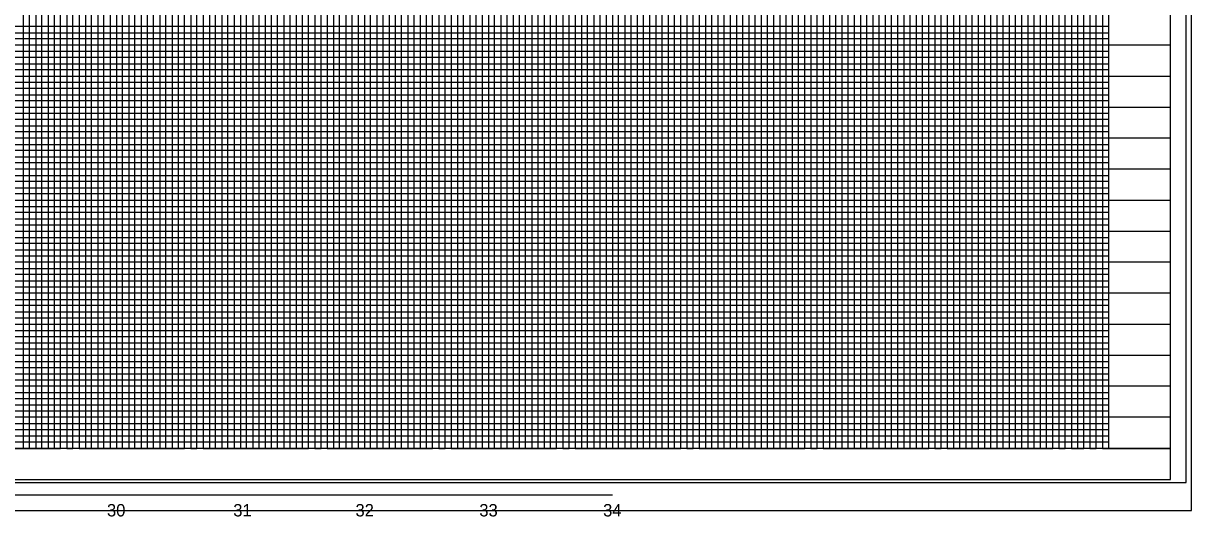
# Model space of a CAD drawing. Extents: x 2345490 to 2436403, y 465165 to 573888.
# Drawn here: x 2383692 to 2384634, y 548958 to 549355 of the extents above; entities that cross this region are included whole.
import ezdxf

# ---------------------------------------------------------------- set-up
doc = ezdxf.new("R2010")
doc.units = 0
for name, color, linetype in [('Old_Level_18', 7, 'Continuous'), ('Old_Level_41', 7, 'Continuous'), ('Old_Level_42', 7, 'Continuous'), ('Old_Level_43', 7, 'Continuous'), ('Old_Level_50', 7, 'Continuous'), ('Old_Level_51', 7, 'Continuous'), ('Old_Level_62', 7, 'Continuous'), ('Old_Level_63', 7, 'Continuous')]:
    doc.layers.add(name, color=color, linetype=linetype)

msp = doc.modelspace()

# ---------------------------------------------------------------- linework, layer by layer
at = {"layer": 'Old_Level_18'}
msp.add_lwpolyline([(2384616.79875, 550037.754), (2383116.79875, 550037.754), (2383116.79875, 548987.754), (2384616.79875, 548987.754)], close=True, dxfattribs=at)
at = {"layer": 'Old_Level_41'}
msp.add_line((2384616.79875, 549012.754), (2383116.79875, 549012.754), dxfattribs=at)
for points in [[(2383641.79875, 549012.754), (2383691.79875, 549012.754), (2383691.79875, 550037.754)], [(2383666.79875, 549012.754), (2383716.79875, 549012.754), (2383716.79875, 550037.754)], [(2383741.79875, 550037.754), (2383741.79875, 549012.754), (2383791.79875, 549012.754), (2383791.79875, 550037.754)], [(2383766.79875, 550037.754), (2383766.79875, 549012.754), (2383816.79875, 549012.754), (2383816.79875, 550037.754)], [(2383841.79875, 550037.754), (2383841.79875, 549012.754), (2383891.79875, 549012.754), (2383891.79875, 550037.754)], [(2383866.79875, 550037.754), (2383866.79875, 549012.754), (2383916.79875, 549012.754), (2383916.79875, 550037.754)], [(2383941.79875, 550037.754), (2383941.79875, 549012.754), (2383991.79875, 549012.754), (2383991.79875, 550037.754)], [(2383966.79875, 550037.754), (2383966.79875, 549012.754), (2384016.79875, 549012.754), (2384016.79875, 550037.754)], [(2384041.79875, 550037.754), (2384041.79875, 549012.754), (2384091.79875, 549012.754), (2384091.79875, 550037.754)], [(2384066.79875, 550037.754), (2384066.79875, 549012.754), (2384116.79875, 549012.754), (2384116.79875, 550037.754)], [(2384141.79875, 550037.754), (2384141.79875, 549012.754), (2384191.79875, 549012.754), (2384191.79875, 550037.754)], [(2384166.79875, 550037.754), (2384166.79875, 549012.754), (2384216.79875, 549012.754), (2384216.79875, 550037.754)], [(2384241.79875, 550037.754), (2384241.79875, 549012.754), (2384291.79875, 549012.754), (2384291.79875, 550037.754)], [(2384266.79875, 550037.754), (2384266.79875, 549012.754), (2384316.79875, 549012.754), (2384316.79875, 550037.754)], [(2384341.79875, 550037.754), (2384341.79875, 549012.754), (2384391.79875, 549012.754), (2384391.79875, 550037.754)], [(2384366.79875, 550037.754), (2384366.79875, 549012.754), (2384416.79875, 549012.754), (2384416.79875, 550037.754)], [(2384441.79875, 549900.204), (2384441.79875, 549012.754), (2384491.79875, 549012.754), (2384491.79875, 549900.204)], [(2384541.79875, 549900.204), (2384541.79875, 549012.754)], [(2384616.79875, 549337.754), (2383116.79875, 549337.754), (2383116.79875, 549287.754), (2384616.79875, 549287.754)], [(2384616.79875, 549262.754), (2383116.79875, 549262.754), (2383116.79875, 549312.754), (2384616.79875, 549312.754)], [(2384616.79875, 549237.754), (2383116.79875, 549237.754), (2383116.79875, 549187.754), (2384616.79875, 549187.754)], [(2384616.79875, 549137.754), (2383116.79875, 549137.754), (2383116.79875, 549087.754), (2384616.79875, 549087.754)], [(2384616.79875, 549062.754), (2383116.79875, 549062.754), (2383116.79875, 549112.754), (2384616.79875, 549112.754)], [(2384616.79875, 549037.754), (2383116.79875, 549037.754)]]:
    msp.add_lwpolyline(points, dxfattribs=at)
at = {"layer": 'Old_Level_42'}
for points in [[(2384466.79875, 549900.204), (2384466.79875, 549012.754), (2384516.79875, 549012.754), (2384516.79875, 549900.204)], [(2384566.79875, 549900.204), (2384566.79875, 549012.754), (2384616.79875, 549012.754)], [(2384616.79875, 549162.754), (2383116.79875, 549162.754), (2383116.79875, 549212.754), (2384616.79875, 549212.754)]]:
    msp.add_lwpolyline(points, dxfattribs=at)
at = {"layer": 'Old_Level_43'}
for points in [[(2383696.79875, 549012.754), (2383696.79875, 550037.754)], [(2383701.79875, 550037.754), (2383701.79875, 549012.754), (2383706.79875, 549012.754), (2383706.79875, 550037.754)], [(2383711.79875, 550037.754), (2383711.79875, 549012.754), (2383721.79875, 549012.754), (2383721.79875, 550037.754)], [(2383726.79875, 550037.754), (2383726.79875, 549012.754), (2383726.79875, 549012.754), (2383731.79875, 549012.754), (2383731.79875, 550037.754)], [(2383736.79875, 550037.754), (2383736.79875, 549012.754), (2383746.79875, 549012.754), (2383746.79875, 550037.754)], [(2383751.79875, 550037.754), (2383751.79875, 549012.754), (2383756.79875, 549012.754), (2383756.79875, 550037.754)], [(2383761.79875, 550037.754), (2383761.79875, 549012.754), (2383771.79875, 549012.754), (2383771.79875, 550037.754)], [(2383776.79875, 550037.754), (2383776.79875, 549012.754), (2383781.79875, 549012.754), (2383781.79875, 550037.754)], [(2383786.79875, 550037.754), (2383786.79875, 549012.754), (2383796.79875, 549012.754), (2383796.79875, 550037.754)], [(2383801.79875, 550037.754), (2383801.79875, 549012.754), (2383806.79875, 549012.754), (2383806.79875, 550037.754)], [(2383811.79875, 550037.754), (2383811.79875, 549012.754), (2383821.79875, 549012.754), (2383821.79875, 550037.754)], [(2383826.79875, 550037.754), (2383826.79875, 549012.754), (2383831.79875, 549012.754), (2383831.79875, 550037.754)], [(2383836.79875, 550037.754), (2383836.79875, 549012.754), (2383846.79875, 549012.754), (2383846.79875, 550037.754)], [(2383851.79875, 550037.754), (2383851.79875, 549012.754), (2383856.79875, 549012.754), (2383856.79875, 550037.754)], [(2383861.79875, 550037.754), (2383861.79875, 549012.754), (2383871.79875, 549012.754), (2383871.79875, 550037.754)], [(2383876.79875, 550037.754), (2383876.79875, 549012.754)], [(2383876.79875, 549012.754), (2383881.79875, 549012.754), (2383881.79875, 550037.154)], [(2383886.79875, 550037.154), (2383886.79875, 549012.754), (2383896.79875, 549012.754), (2383896.79875, 550037.754)], [(2383901.79875, 550037.754), (2383901.79875, 549012.754), (2383906.79875, 549012.754), (2383906.79875, 550037.754)], [(2383911.79875, 550037.754), (2383911.79875, 549012.754), (2383921.79875, 549012.754), (2383921.79875, 550037.754)], [(2383926.79875, 550037.754), (2383926.79875, 549012.754), (2383931.79875, 549012.754), (2383931.79875, 550037.754)], [(2383936.79875, 550037.754), (2383936.79875, 549012.754), (2383946.79875, 549012.754), (2383946.79875, 550037.754)], [(2383951.79875, 550037.754), (2383951.79875, 549012.754), (2383956.79875, 549012.754), (2383956.79875, 550037.754)], [(2383961.79875, 550037.754), (2383961.79875, 549012.754), (2383971.79875, 549012.754), (2383971.79875, 550037.754)], [(2383976.79875, 550037.754), (2383976.79875, 549012.754), (2383981.79875, 549012.754), (2383981.79875, 550037.754)], [(2383986.79875, 550037.754), (2383986.79875, 549012.754), (2383996.79875, 549012.754), (2383996.79875, 550037.754)], [(2384001.79875, 550037.754), (2384001.79875, 549012.754), (2384006.79875, 549012.754), (2384006.79875, 550037.754)], [(2384011.79875, 550037.754), (2384011.79875, 549012.754), (2384021.79875, 549012.754), (2384021.79875, 550037.754)], [(2384026.79875, 550037.754), (2384026.79875, 549012.754), (2384031.79875, 549012.754), (2384031.79875, 550037.754)], [(2384036.79875, 550037.754), (2384036.79875, 549012.754), (2384046.79875, 549012.754), (2384046.79875, 550037.754)], [(2384051.79875, 550037.754), (2384051.79875, 549012.754), (2384056.79875, 549012.754), (2384056.79875, 550037.754)], [(2384061.79875, 550037.754), (2384061.79875, 549012.754), (2384071.79875, 549012.754), (2384071.79875, 550037.754)], [(2384076.79875, 550037.754), (2384076.79875, 549012.754), (2384081.79875, 549012.754), (2384081.79875, 550037.754)], [(2384086.79875, 550037.754), (2384086.79875, 549012.754), (2384096.79875, 549012.754), (2384096.79875, 550037.754)], [(2384101.79875, 550037.754), (2384101.79875, 549012.754), (2384106.79875, 549012.754), (2384106.79875, 550037.754)], [(2384111.79875, 550037.754), (2384111.79875, 549012.754), (2384121.79875, 549012.754), (2384121.79875, 550037.754)], [(2384126.79875, 550037.754), (2384126.79875, 549012.754), (2384131.79875, 549012.754), (2384131.79875, 550037.754)], [(2384136.79875, 550037.754), (2384136.79875, 549012.754), (2384146.79875, 549012.754), (2384146.79875, 550037.754)], [(2384151.79875, 550037.754), (2384151.79875, 549012.754), (2384156.79875, 549012.754), (2384156.79875, 550037.754)], [(2384161.79875, 550037.754), (2384161.79875, 549012.754), (2384171.79875, 549012.754), (2384171.79875, 550037.754)], [(2384176.79875, 550037.754), (2384176.79875, 549012.754), (2384181.79875, 549012.754), (2384181.79875, 550037.754)], [(2384186.79875, 550037.754), (2384186.79875, 549012.754)], [(2384186.79875, 549012.754), (2384196.79875, 549012.754), (2384196.79875, 550037.754)], [(2384201.79875, 550037.754), (2384201.79875, 549012.754), (2384206.79875, 549012.754), (2384206.79875, 550037.754)], [(2384211.79875, 550037.754), (2384211.79875, 549012.754), (2384221.79875, 549012.754), (2384221.79875, 550037.754)], [(2384226.79875, 550037.754), (2384226.79875, 549012.754), (2384231.79875, 549012.754), (2384231.79875, 550037.754)], [(2384236.79875, 550037.754), (2384236.79875, 549012.754), (2384246.79875, 549012.754), (2384246.79875, 550037.754)], [(2384251.79875, 550037.754), (2384251.79875, 549012.754), (2384256.79875, 549012.754), (2384256.79875, 550037.754)], [(2384261.79875, 550037.754), (2384261.79875, 549012.754), (2384271.79875, 549012.754), (2384271.79875, 550037.754)], [(2384276.79875, 550037.754), (2384276.79875, 549012.754), (2384281.79875, 549012.754), (2384281.79875, 550037.754)], [(2384286.79875, 550037.754), (2384286.79875, 549012.754), (2384296.79875, 549012.754), (2384296.79875, 550037.754)], [(2384301.79875, 550037.754), (2384301.79875, 549012.754), (2384306.79875, 549012.754), (2384306.79875, 550037.754)], [(2384311.79875, 550037.754), (2384311.79875, 549012.754), (2384321.79875, 549012.754), (2384321.79875, 550037.754)], [(2384326.79875, 550037.754), (2384326.79875, 549012.754), (2384331.79875, 549012.754), (2384331.79875, 550037.754)], [(2384336.79875, 550037.754), (2384336.79875, 549012.754), (2384346.79875, 549012.754), (2384346.79875, 550037.754)], [(2384351.79875, 550037.754), (2384351.79875, 549012.754), (2384356.79875, 549012.754), (2384356.79875, 550037.754)], [(2384361.79875, 550037.754), (2384361.79875, 549012.754), (2384371.79875, 549012.754), (2384371.79875, 550037.754)], [(2384376.79875, 550037.754), (2384376.79875, 549012.754), (2384381.79875, 549012.754), (2384381.79875, 550037.754)], [(2384386.79875, 550037.754), (2384386.79875, 549012.754), (2384396.79875, 549012.754), (2384396.79875, 550037.754)], [(2384401.79875, 550037.754), (2384401.79875, 549012.754), (2384406.79875, 549012.754), (2384406.79875, 550037.754)], [(2384411.79875, 550037.754), (2384411.79875, 549012.754), (2384421.79875, 549012.754), (2384421.79875, 549900.204)], [(2384426.79875, 549900.204), (2384426.79875, 549012.754), (2384431.79875, 549012.754), (2384431.79875, 549900.204)], [(2384436.79875, 549900.204), (2384436.79875, 549012.754), (2384446.79875, 549012.754), (2384446.79875, 549900.204)], [(2384451.79875, 549900.204), (2384451.79875, 549012.754), (2384456.79875, 549012.754), (2384456.79875, 549900.204)], [(2384461.79875, 549900.204), (2384461.79875, 549012.754), (2384471.79875, 549012.754), (2384471.79875, 549900.204)], [(2384476.79875, 549900.204), (2384476.79875, 549012.754), (2384481.79875, 549012.754), (2384481.79875, 549900.204)], [(2384486.79875, 549900.204), (2384486.79875, 549012.754), (2384496.79875, 549012.754), (2384496.79875, 549900.204)], [(2384501.79875, 549900.204), (2384501.79875, 549012.754)], [(2384501.79875, 549012.754), (2384506.79875, 549012.754), (2384506.79875, 549900.204)], [(2384511.79875, 549900.204), (2384511.79875, 549012.754), (2384521.79875, 549012.754), (2384521.79875, 549900.204)], [(2384526.79875, 549900.204), (2384526.79875, 549012.754), (2384531.79875, 549012.754), (2384531.79875, 549900.204)], [(2384536.79875, 549900.204), (2384536.79875, 549012.754), (2384546.79875, 549012.754), (2384546.79875, 549900.204)], [(2384551.79875, 549900.204), (2384551.79875, 549012.754), (2384556.79875, 549012.754), (2384556.79875, 549900.204)], [(2384561.79875, 549900.204), (2384561.79875, 549012.754), (2384571.79875, 549012.754)], [(2384566.79875, 549352.754), (2383166.79875, 549352.754), (2383166.79875, 549347.754), (2384566.79875, 549347.754)], [(2384566.79875, 549342.754), (2383166.79875, 549342.754), (2383166.79875, 549332.754), (2384566.79875, 549332.754)], [(2384566.79875, 549327.754), (2383166.79875, 549327.754), (2383166.79875, 549322.754), (2384566.79875, 549322.754)], [(2384566.79875, 549317.754), (2383166.79875, 549317.754), (2383166.79875, 549307.754), (2384566.79875, 549307.754)], [(2384566.79875, 549302.754), (2383166.79875, 549302.754), (2383166.79875, 549297.754), (2384566.79875, 549297.754)], [(2384566.79875, 549292.754), (2383166.79875, 549292.754), (2383166.79875, 549282.754), (2384566.79875, 549282.754)], [(2384566.79875, 549277.754), (2383166.79875, 549277.754), (2383166.79875, 549272.754), (2384566.79875, 549272.754)], [(2384566.79875, 549267.754), (2383166.79875, 549267.754), (2383166.79875, 549257.754), (2384566.79875, 549257.754)], [(2384566.79875, 549252.754), (2383166.79875, 549252.754), (2383166.79875, 549247.754), (2384566.79875, 549247.754)], [(2384566.79875, 549242.754), (2383166.79875, 549242.754), (2383166.79875, 549232.754), (2384566.79875, 549232.754)], [(2384566.79875, 549227.754), (2383166.79875, 549227.754), (2383166.79875, 549222.754), (2384566.79875, 549222.754)], [(2384566.79875, 549217.754), (2383166.79875, 549217.754)], [(2383166.79875, 549207.754), (2384566.79875, 549207.754)], [(2384566.79875, 549202.754), (2383166.79875, 549202.754), (2383166.79875, 549197.754), (2384566.79875, 549197.754)], [(2384566.79875, 549192.754), (2383166.79875, 549192.754)], [(2383166.79875, 549182.754), (2384566.79875, 549182.754)], [(2384566.79875, 549177.754), (2383166.79875, 549177.754), (2383166.79875, 549172.754), (2384566.79875, 549172.754)], [(2384566.79875, 549167.754), (2383166.79875, 549167.754), (2383166.79875, 549157.754), (2384566.79875, 549157.754)], [(2384566.79875, 549152.754), (2383166.79875, 549152.754), (2383166.79875, 549147.754), (2384566.79875, 549147.754)], [(2384566.79875, 549142.754), (2383166.79875, 549142.754), (2383166.79875, 549132.754), (2384566.79875, 549132.754)], [(2384566.79875, 549127.754), (2383166.79875, 549127.754), (2383166.79875, 549122.754), (2384566.79875, 549122.754)], [(2384566.79875, 549117.754), (2383166.79875, 549117.754), (2383166.79875, 549107.754), (2384566.79875, 549107.754)], [(2384566.79875, 549102.754), (2383166.79875, 549102.754), (2383166.79875, 549097.754), (2384566.79875, 549097.754)], [(2384566.79875, 549092.754), (2383166.79875, 549092.754), (2383166.79875, 549082.754), (2384566.79875, 549082.754)], [(2384566.79875, 549077.754), (2383166.79875, 549077.754), (2383166.79875, 549072.754), (2384566.79875, 549072.754)], [(2384566.79875, 549067.754), (2383166.79875, 549067.754), (2383166.79875, 549057.754), (2384566.79875, 549057.754)], [(2384566.79875, 549052.754), (2383166.79875, 549052.754), (2383166.79875, 549047.754), (2384566.79875, 549047.754)], [(2384566.79875, 549042.754), (2383166.79875, 549042.754), (2383166.79875, 549032.754), (2384566.79875, 549032.754)], [(2384566.79875, 549027.754), (2383166.79875, 549027.754), (2383166.79875, 549022.754), (2384566.79875, 549022.754)], [(2384566.79875, 549017.754), (2383166.79875, 549017.754)]]:
    msp.add_lwpolyline(points, dxfattribs=at)
at = {"layer": 'Old_Level_50'}
msp.add_lwpolyline([(2384629.29875, 550040.304), (2382962.79875, 550040.304), (2382962.79875, 548985.204), (2384629.29875, 548985.204)], close=True, dxfattribs=at)
at = {"layer": 'Old_Level_51'}
msp.add_lwpolyline([(2384633.79875, 550062.754), (2382949.79875, 550062.754), (2382949.79875, 548962.754), (2384633.79875, 548962.754)], close=True, dxfattribs=at)
at = {"layer": 'Old_Level_63'}
msp.add_line((2381766.79875, 548975.3665), (2384166.79875, 548975.3665), dxfattribs=at)

# ---------------------------------------------------------------- texts
at = {"layer": 'Old_Level_62'}
for s, p in [('30', (2383759.1855, 548957.8665)), ('31', (2383861.025, 548957.8665)), ('32', (2383959.57325, 548957.8665)), ('33', (2384059.408, 548957.8665)), ('34', (2384159.2505, 548957.8665))]:
    msp.add_text(s, height=10.000001, dxfattribs=at).set_placement(p)

doc.saveas('drawing.dxf')
